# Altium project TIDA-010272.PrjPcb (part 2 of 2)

## Sheet Power.SchDoc
size 431 x 279 mm; Date: Not shown in title block; ApprovedBy: Not shown in title block; CheckedBy: Not shown in title block; Author: Not shown in title block; CompanyName: Not shown in title block; Engineer: Not shown in title block; Organization: Not shown in title block; Address1: Not shown in title block; Address2: Not shown in title block; Address3: Not shown in title block; Address4: Not shown in title block; DocumentNumber: 2; Revision: Use project parameter SCH_Rev; SheetNumber: 9; SheetTotal: 10; PageSetup: Record=PageOptions¦CenterHorizontal=True¦CenterVertical=True¦PrintScale=1.00¦XCorrection=1.00¦YCorrection=1.00¦PrintKind=0¦BorderSize=5000000¦LeftOffset=0¦BottomOffset=0¦Orientation=2¦PaperLength=1000¦PaperWidth=1000¦Scale=100¦PaperSource=15¦PrintQuality=600¦MediaType=1¦DitherType=10¦PaperKind=Letter¦PrintScaleMode=1; EVM_orderable: N/A
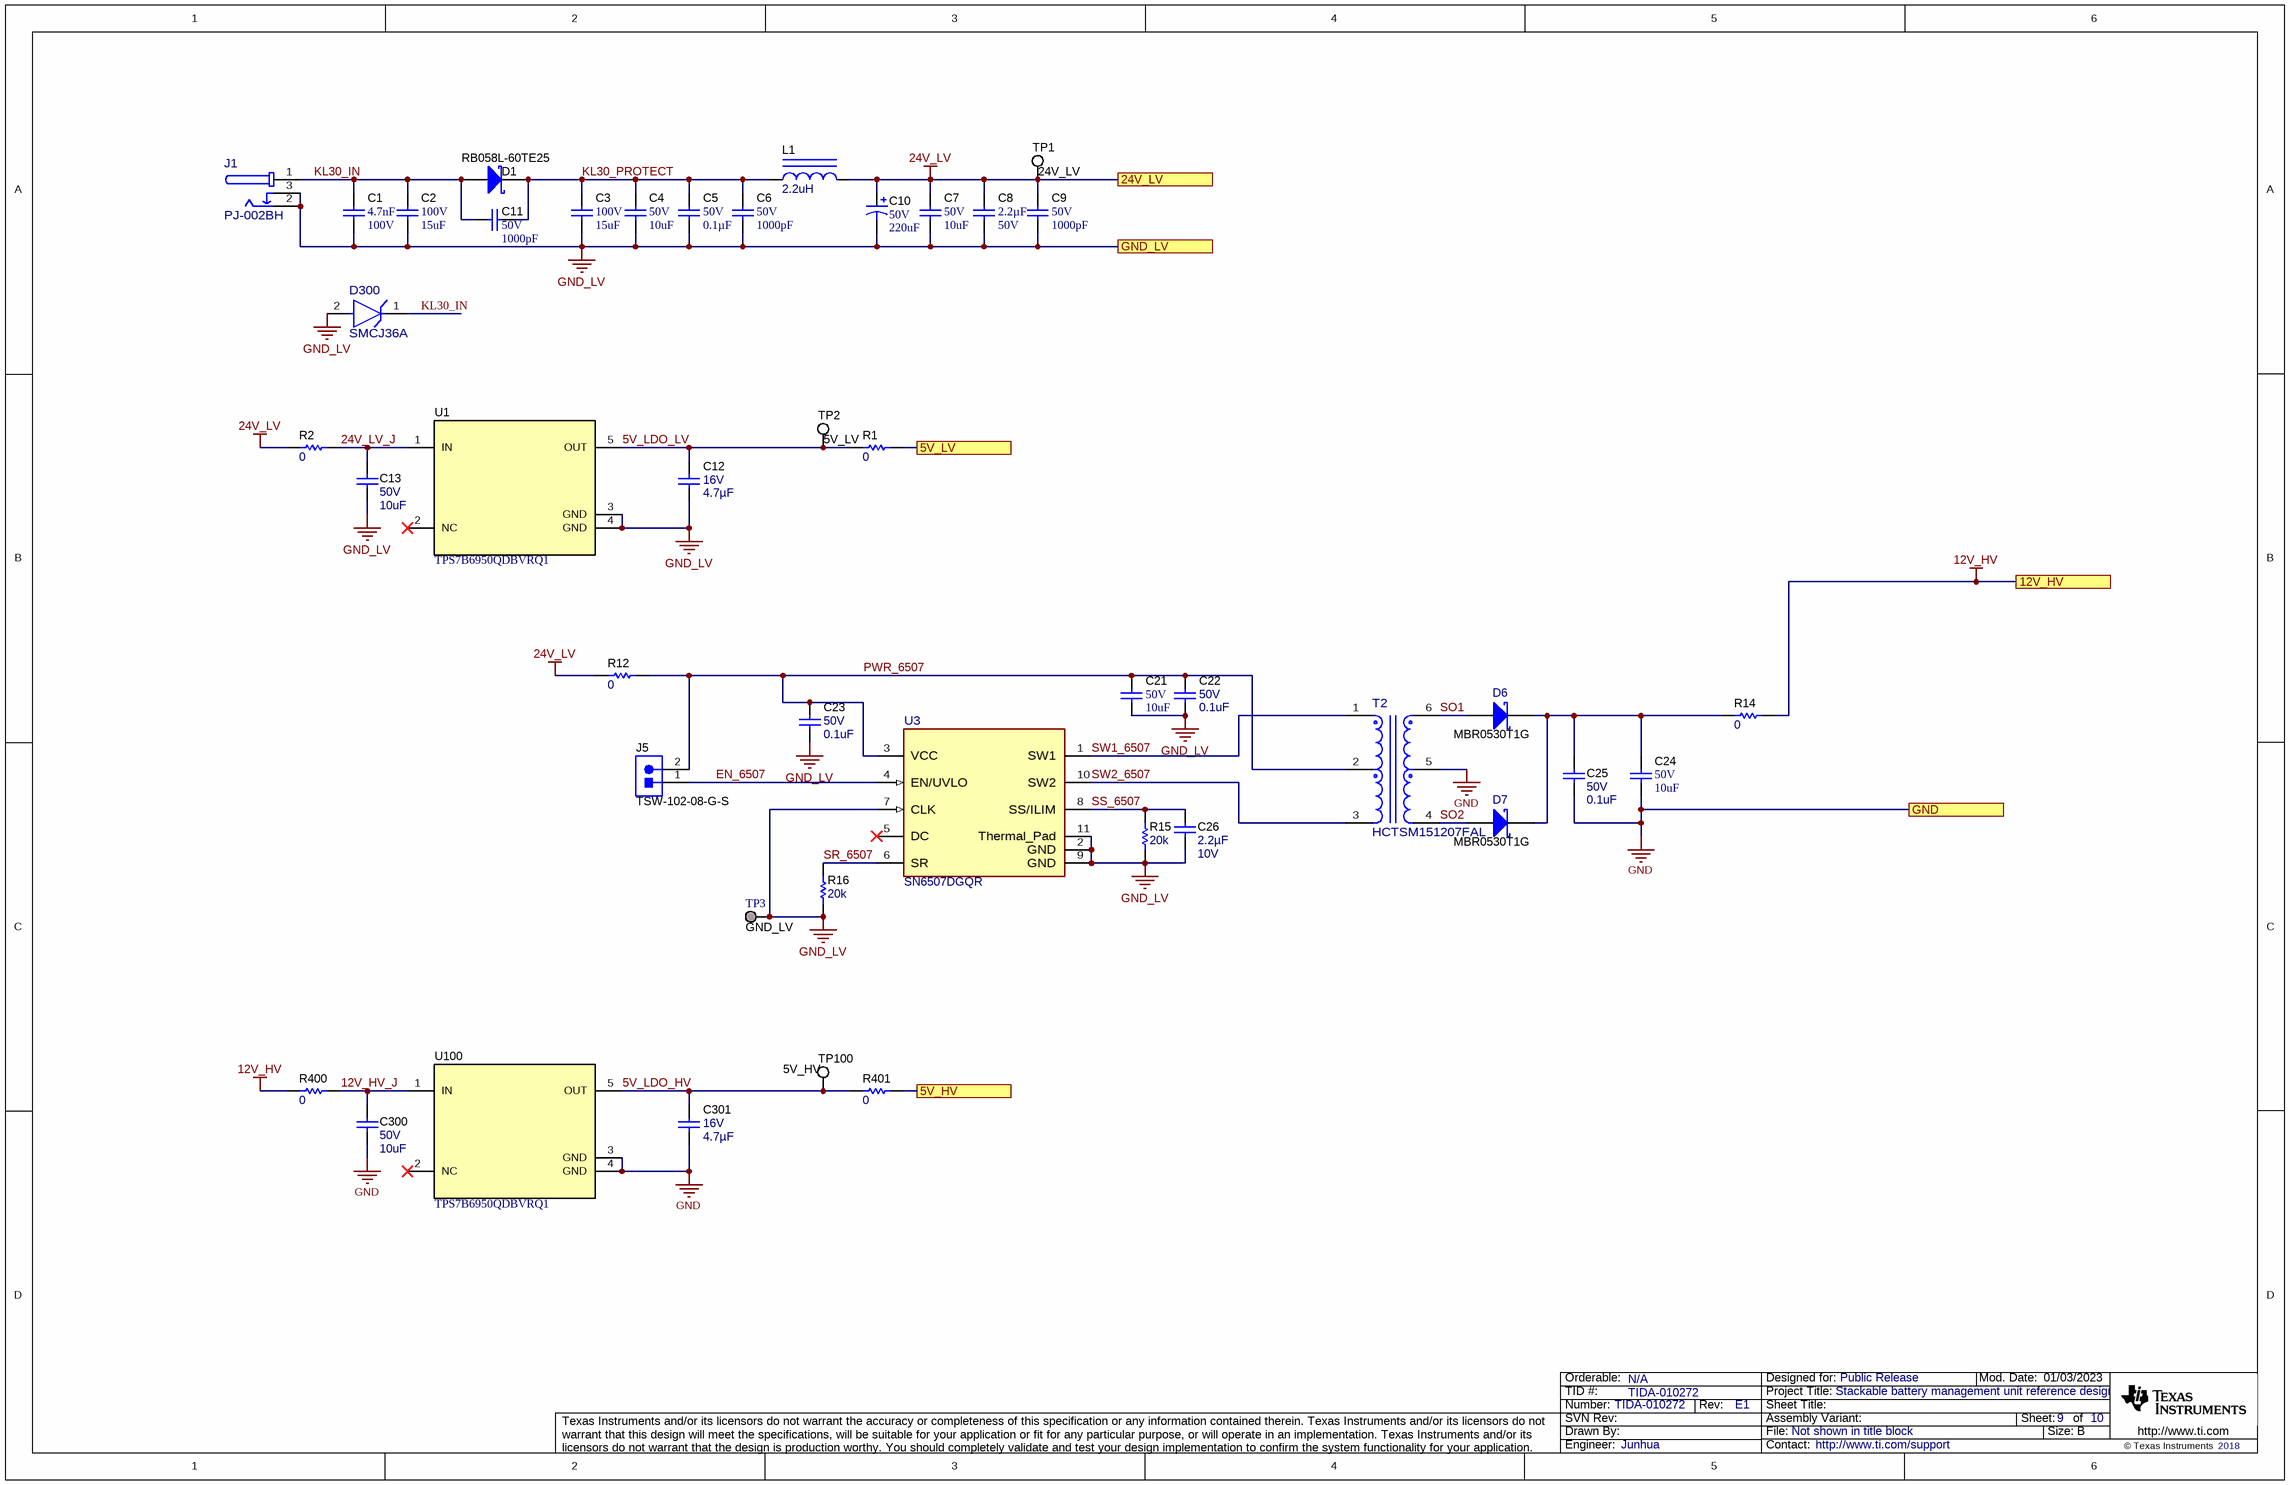
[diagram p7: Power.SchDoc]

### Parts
C1  Cap_F: 4.7nF  VDC_V: 100V  [0603]  (hidden comment: CGA3E2X7R2A472K080AA)
C2  VDC_V: 100V  ValueDisplayed: 15uF  [2220_280]  (hidden comment: CGA9P3X7S2A156M250KB)
C3  VDC_V: 100V  ValueDisplayed: 15uF  [2220_280]  (hidden comment: CGA9P3X7S2A156M250KB)
C4  VDC_V: 50V  ValueDisplayed: 10uF  [1210_280]  (hidden comment: CGA6P3X7S1H106K250AB)
C5  VDC_V: 50V  ValueDisplayed: 0.1µF  [0603]  (hidden comment: CGA3E3X8R1H104M080AB)
C6  VDC_V: 50V  ValueDisplayed: 1000pF  [0402]  (hidden comment: CGA2B2C0G1H102J050BA)
C7  VDC_V: 50V  ValueDisplayed: 10uF  [1210_280]  (hidden comment: CGA6P3X7S1H106K250AB)
C8  Cap_F: 2.2µF  VDC_V: 50V  [0805_HV]  (hidden comment: CGA4J3X7R1H225K125AB)
C9  VDC_V: 50V  ValueDisplayed: 1000pF  [0402]  (hidden comment: CGA2B2C0G1H102J050BA)
C10  VDC_V: 50V  ValueDisplayed: 220uF  [SM_RADIAL_G]  (hidden comment: EEE-FK1H221GP)
C11  VDC_V: 50V  ValueDisplayed: 1000pF  [0402]  (hidden comment: GRM1555C1H102JA01D)
C12  VDC_V: 16V  ValueDisplayed: 4.7µF  [0603]  (hidden comment: GRT188R61C475KE13D)
C13  VDC_V: 50V  ValueDisplayed: 10uF  [1206_180]  (hidden comment: GRT31CR61H106KE01L)
C21  VDC_V: 50V  ValueDisplayed: 10uF  [1210_280]  (hidden comment: CGA6P3X7S1H106K250AB)
C22  VDC_V: 50V  ValueDisplayed: 0.1uF  [0402]  (hidden comment: GCM155R71H104KE02D)
C23  VDC_V: 50V  ValueDisplayed: 0.1uF  [0402]  (hidden comment: GCM155R71H104KE02D)
C24  VDC_V: 50V  ValueDisplayed: 10uF  [1210_280]  (hidden comment: CGA6P3X7S1H106K250AB)
C25  VDC_V: 50V  ValueDisplayed: 0.1uF  [0402]  (hidden comment: GCM155R71H104KE02D)
C26  Cap_F: 2.2µF  VDC_V: 10V  [0603]  (hidden comment: GRM188R71A225KE15J)
C300  VDC_V: 50V  ValueDisplayed: 10uF  [1206_180]  (hidden comment: GRT31CR61H106KE01L)
C301  VDC_V: 16V  ValueDisplayed: 4.7µF  [0603]  (hidden comment: GRT188R61C475KE13D)
D1  RB058L-60TE25  [SMA]
D6  MBR0530T1G  [SOD-123]
D7  MBR0530T1G  [SOD-123]
D300  SMCJ36A  [FP-SMCJ36A_DO-214AB-MFG]
J1  PJ-002BH  [FP-PJ-002BH_PTH_POWER_CONN_14MM4_9MM0-MFG]
J5  TSW-102-08-G-S  [Samtec_TSW-102-08-x-S]
L1  ValueDisplayed: 2.2uH  [IHLP-1616BZ]  (hidden comment: IHLP1616BZER2R2M01)
R1  ValueDisplayed: 0  [0603]  (hidden comment: CRCW06030000Z0EA)
R2  ValueDisplayed: 0  [0603]  (hidden comment: CRCW06030000Z0EA)
R12  ValueDisplayed: 0  [0603]  (hidden comment: CRCW06030000Z0EA)
R14  ValueDisplayed: 0  [0603]  (hidden comment: CRCW06030000Z0EA)
R15  ValueDisplayed: 20k  [0402]  (hidden comment: CRCW040220K0JNED)
R16  ValueDisplayed: 20k  [0402]  (hidden comment: CRCW040220K0JNED)
R400  ValueDisplayed: 0  [0603]  (hidden comment: CRCW06030000Z0EA)
R401  ValueDisplayed: 0  [0603]  (hidden comment: CRCW06030000Z0EA)
T2  HCTSM151207FAL  [FP-HCTSM151207FAL_SMT_XFRMR_21MM3_15MM0-MFG]
TP1  24V_LV  [Keystone5012]
TP2  5V_LV  [Keystone5012]
TP3  GND_LV  [Keystone1598-2]
TP100  5V_HV  [Keystone5012]
U1  TPS7B6950QDBVRQ1  [DBV0005A_N]
U3  SN6507DGQR  [DGQ0010D-C01-MFG]
U100  TPS7B6950QDBVRQ1  [DBV0005A_N]

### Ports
5V_HV, 5V_LV, 12V_HV, 24V_LV, GND, GND_LV

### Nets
12V_HV: R14.2 R400.1 ; port 12V_HV  [project net HV12]
24V_LV: C7.1 C8.1 C9.1 C10.1(+) L1.2 R2.1 R12.1 TP1.1 ; port 24V_LV
GND: C24.2 C25.2 C300.2 C301.2 T2.5 U100.3(GND) U100.4(GND) ; port GND
GND_LV: C1.2 C2.2 C3.2 C4.2 C5.2 C6.2 C7.2 C8.2 C9.2 C10.2(-) C12.2 C13.2 C21.2 C22.2 C23.2 C26.2 D300.2(ANODE) J1.2 J1.3 R15.1 R16.1 TP3.1 U1.3(GND) U1.4(GND) U3.2(GND) U3.7(CLK) U3.9(GND) U3.11(Thermal_Pad) ; port GND_LV
5V_HV: R401.2 ; port 5V_HV
5V_LDO_HV: C301.1 R401.1 TP100.1 U100.5(OUT)
5V_LDO_LV: C12.1 R1.1 TP2.1 U1.5(OUT)
5V_LV: R1.2 ; port 5V_LV
12V_HV_J: C300.1 R400.2 U100.1(IN)
24V_LV_J: C13.1 R2.2 U1.1(IN)
EN_6507: J5.1 U3.4(EN/UVLO)
KL30_IN: C1.1 C2.1 C11.2 D1.2(A) D300.1(CATHODE) J1.1
KL30_PROTECT: C3.1 C4.1 C5.1 C6.1 C11.1 D1.1(K) L1.1
PWR_6507: C21.1 C22.1 C23.1 J5.2 R12.2 T2.2 U3.3(VCC)
SO1: D6.2(A) T2.6
SO2: D7.2(A) T2.4
SR_6507: R16.2 U3.6(SR)
SS_6507: C26.1 R15.2 U3.8(SS/ILIM)
SW1_6507: T2.1 U3.1(SW1)
SW2_6507: T2.3 U3.10(SW2)
NetC24_1: C24.1 C25.1 D6.1(K) D7.1(K) R14.1

Not connected (* = marked no-connect by the designer): U1 2(NC)*; U3 5(DC)*; U100 2(NC)*

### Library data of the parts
C1 = CMP-0007088-4: CAP, CERM, 4700 pF, 100 V, +/- 10%, X7R, AEC-Q200 Grade 1, 0603; Manufacturer: TDK; TaMin_C: -55°C; ESR_ohm: 0.469862; Polarized: N; SizeAreaWB_mm2: 4.68; Value1: 0.469862 ohm; U/M: EA; Value: 4700pF; TaMax_C: 125°C; SizeZ_mm: 1; SizeX_mm: 1.6; SizeY_mm: 0.8; SizeArea_mm2: 1.28; AEC Qualified: Y; IRMS_A: 323.35mA; AEC Category: Q200
C2 C3 = CMP-0009420-2: CAP, CERM, 15 uF, 100 V, +/- 20%, X7S, AEC-Q200 Grade 1, 2220; Manufacturer: TDK; TaMin_C: -55°C; ESR_ohm: 2.642m; Polarized: N; SizeAreaWB_mm2: 53.9; Value1: 0.002642 ohm; U/M: EA; Value: 15uF; TaMax_C: 125°C; SizeZ_mm: 2.8; SizeX_mm: 5.7; SizeY_mm: 5; SizeArea_mm2: 28.5; AEC Qualified: Y; Cap_F: 15µF; IRMS_A: 5.61617A; AEC Grade: 1; AEC Category: Q200
C4 C7 C21 C24 = CMP-0009164-2: CAP, CERM, 10 uF, 50 V, +/- 10%, X7S, AEC-Q200 Grade 1, 1210; Manufacturer: TDK; TaMin_C: -55°C; ESR_ohm: 2.827m; Polarized: N; SizeAreaWB_mm2: 14.7; Value1: 0.002827 ohm; U/M: EA; Value: 10uF; TaMax_C: 125°C; SizeZ_mm: 2.8; SizeX_mm: 3.2; SizeY_mm: 2.5; SizeArea_mm2: 8; AEC Qualified: Y; Cap_F: 10µF; IRMS_A: 4.37286A; AEC Grade: 1; AEC Category: Q200
C5 = CMP-0084240-1: CAP, CERM, 0.1 µF, 50 V,+/- 20%, X8R, AEC-Q200 Grade 0, 0603; Manufacturer: TDK; TaMin_C: -55°C; Polarized: N; SizeAreaWB_mm2: 4.68; U/M: EA; Value: 0.1uF; TaMax_C: 150°C; SizeZ_mm: 1; SizeX_mm: 1.6; SizeY_mm: 0.8; SizeArea_mm2: 1.28; AEC Qualified: Y; Cap_F: 100nF; AEC Grade: 0; AEC Category: Q200
C6 C9 = CMP-0006309-2: CAP, CERM, 1000 pF, 50 V, +/- 5%, C0G/NP0, AEC-Q200 Grade 1, 0402; Manufacturer: TDK; TaMin_C: -55°C; Polarized: N; SizeAreaWB_mm2: 3; Value1: Unknown; U/M: EA; Value: 1000pF; TaMax_C: 125°C; SizeZ_mm: 0.6; SizeX_mm: 1; SizeY_mm: 0.5; AEC Qualified: Y; Cap_F: 1nF; AEC Category: Q200
C8 = CMP-0007977-2: CAP, CERM, 2.2 uF, 50 V, +/- 10%, X7R, AEC-Q200 Grade 1, 0805; Manufacturer: TDK; TaMin_C: -55°C; ESR_ohm: 3.288m; Polarized: N; SizeAreaWB_mm2: 6.75; Value1: 0.003288 ohm; U/M: EA; Value: 2.2uF; TaMax_C: 125°C; SizeZ_mm: 1.45; SizeX_mm: 2; SizeY_mm: 1.25; Cap_Case: 0805; SizeArea_mm2: 2.5; AEC Qualified: Y; IRMS_A: 3.60029A; AEC Grade: 1; AEC Category: Q200
C10 = CMP-0011180-2: CAP, AL, 220 uF, 50 V, +/- 20%, 0.18 ohm, AEC-Q200 Grade 2, SMD; Manufacturer: Panasonic; TaMin_C: -55°C; ESR_ohm: 1.8d; Polarized: Y; SizeAreaWB_mm2: 172.2; U/M: EA; Value: 220uF; TaMax_C: 105°C; SizeZ_mm: 10.2; SizeX_mm: 12; SizeY_mm: 10.3; Cap_Case: G; SizeArea_mm2: 123.6; CompType: Capacitor; Cap_F: 220µF; IRMS_A: 6.7dA; AEC Grade: 2; AEC Category: Q200
C11 = CMP-0006412-2: CAP, CERM, 1000 pF, 50 V, +/- 5%, C0G/NP0, 0402; Manufacturer: MuRata; TaMin_C: -55°C; Polarized: N; SizeAreaWB_mm2: 3; Value1: Unknown; U/M: EA; Value: 1000pF; TaMax_C: 125°C; SizeZ_mm: 0.6; SizeX_mm: 1; SizeY_mm: 0.5; Cap_F: 1nF; AEC Category: Q200
C12 C301 = CMP-0081052-1: CAP, CERM, 4.7 µF, 16 V,+/- 10%, X5R, AEC-Q200 Grade 3, 0603; Manufacturer: MuRata; SizeAreaWB_mm2: 4.68; SizeArea_mm2: 1.28; AEC Qualified: Y; AEC Category: Q200; Value: 4.7uF; TaMax_C: 85°C; SizeZ_mm: 1; AEC Grade: 3; Polarized: N; TaMin_C: -55°C; SizeY_mm: 0.8; U/M: EA; SizeX_mm: 1.6
C13 C300 = CMP-0009015-2: CAP, CERM, 10 uF, 50 V, +/- 10%, X5R, AEC-Q200 Grade 1, 1206; Manufacturer: MuRata; TaMin_C: -55°C; Polarized: N; SizeAreaWB_mm2: 10.92; Value1: Unknown; U/M: EA; Value: 10uF; TaMax_C: 85°C; SizeZ_mm: 1.8; SizeX_mm: 3.2; SizeY_mm: 1.6; Cap_Case: 1206; SizeArea_mm2: 5.12; AEC Qualified: Y; Cap_F: 10µF; AEC Grade: 1; AEC Category: Q200
C22 C23 C25 = CMP-0006356-2: CAP, CERM, 0.1 uF, 50 V, +/- 10%, X7R, AEC-Q200 Grade 1, 0402; Manufacturer: MuRata; TaMin_C: -55°C; Polarized: N; SizeAreaWB_mm2: 3; Value1: Unknown; U/M: EA; Value: 0.1uF; TaMax_C: 125°C; SizeZ_mm: 0.6; SizeX_mm: 1; SizeY_mm: 0.5; AEC Qualified: Y; Cap_F: 100nF; AEC Category: Q200
C26 = CMP-0084284-1: CAP, CERM, 2.2 µF, 10 V,+/- 10%, X7R, AEC-Q200 Grade 1, 0603; Manufacturer: MuRata; SizeAreaWB_mm2: 4.68; Polarized: N; AEC Qualified: Y; SizeX_mm: 1.6; SizeZ_mm: 1; SizeY_mm: 0.8; U/M: EA; TaMin_C: -55°C; Value: 2.2uF; AEC Category: Q200; TaMax_C: 125°C; SizeArea_mm2: 1.28
D1 = CMP-0028854-2: Diode, Schottky, 60 V, 3 A, AEC-Q101, SMA; Manufacturer: Rohm; Value1: 3A; AEC Category: Q101; Green_REACh: Incomplete; TJmax_C: 150°C; SizeArea_mm2: 16.3228; Vf_V: 640mV; SizeZ_mm: 2.87; Value2: 0.64V; Value: 60V; SizeX_mm: 5.59; AEC Qualified: Y; Green_Lifecycle: Not Set; SizeAreaWB_mm2: 37.3428; SizeY_mm: 2.92
D6 D7 = CMP-0028525-2: Diode, Schottky, 30 V, 0.5 A, SOD-123; Manufacturer: ON Semiconductor; Value: 30V; SizeZ_mm: 1.35; SizeAreaWB_mm2: 13.095; Value2: 0.43V; Green_REACh: Passed; Io_A: 500mA; SizeArea_mm2: 6.545; TJmax_C: 125°C; Green_Lifecycle: Active; RJC_CperW: 150; SizeX_mm: 3.85; AEC Category: Q101; SizeY_mm: 1.7; Vf_V: 430mV; Value1: 0.5A
D300 = CMP-0089183-1: TVS DIODE 36VWM 58.1VC SMC; Manufacturer: Littelfuse; Breakdown Voltage: 40V; TJmax_C: +150°C; SizeZ_mm: 2.62mm; Direction: Unidirectional; Ppk: 1.5kW; Number Of Channels: 1; AEC Qualified: No; Clamping Voltage: 58.1V; VRWM: 36V; Ipp: 25.9A
J1 = CMP-0091947-1: Manufacturer: CUI Devices; AEC Qualified: No; SizeZ_mm: 11.2mm; Conn Orientation: Right Angle; ContactFinish: Nickel; Voltage_V: 24V; Conn Gender: Male; Current_A: 5A
J5 = CMP-0077643-1: Header, 2.54mm, 2x1, Gold, TH; Manufacturer: Samtec; Pitch_mm: 2.54; Gender: Male; Cert_CSA: Y; Current_A: 5.7A; Voltage_V: 550V; Row_Count: 1
L1 = CMP-0063278-1: Inductor, Shielded Drum Core, Powdered Iron, 2.2 uH, 2.85 A, 0.08 ohm, SMD; Manufacturer: Vishay-Dale; Isat: 6A @ 20% inductance drop; Irms: 2.85A @ 40C rise; Green_Lifecycle: Active; SizeAreaWB_mm2: 27.577; DCR_ohm: 0.08; Green_REACh: Passed; Value: 2.2uH; Imax_A: 2.85A; SizeZ_mm: 2; SizeX_mm: 4.45; SizeY_mm: 4.06; SizeArea_mm2: 18.067; Ind_H: 2.2µH; AEC Category: Q200
R1 R2 R12 R14 R400 R401 = CMP-0025697-4: RES, 0, 5%, 0.1 W, AEC-Q200 Grade 0, 0603; Manufacturer: Vishay-Dale; Power_W: 100mW; TempCo: 200 ppm/C; Value_Code: 0000; Value: 0; EIA_Code: E24; SizeX_mm: 1.6; SizeY_mm: 0.8; SizeZ_mm: 1; Value2: 0.1W; SizeArea_mm2: 1.28; AEC Qualified: Y; VDC_V: 75V; AEC Category: Q200
R15 R16 = CMP-0026875-3: RES, 20 k, 5%, 0.063 W, AEC-Q200 Grade 0, 0402; Manufacturer: Vishay-Dale; Power_W: 63mW; TempCo: 200 ppm/C; Value_Code: 20k0; Value: 20k; EIA_Code: E24; SizeX_mm: 1; SizeY_mm: 0.5; SizeZ_mm: 0.6; Value2: 0.063W; AEC Qualified: Y; VDC_V: 50V; AEC Category: Q200; AEC Grade: 0
T2 = CMP-0120536-1: High Clearance and Creepage Transformer; Manufacturer: Bourns; DCR_ohm: 1.5; Ind_H: 400µH; Ns1toNp: 0.583; Rsec1_ohm: 1; SizeZ_mm: 10.1mm; AEC Qualified: Yes; AEC Grade: Grade 0; Frequency_Fixed: 100-2000kHz; Voltage_Isolation_Vrms: 7.64kVDC
TP1 TP2 TP100 = CMP-0055149-1: Test Point, Multipurpose, White, TH; PartNumber: 5012; Manufacturer: Keystone; ContactFinish: Silver; CNHeader: FALSE; Green_Lifecycle: Active; Green_REACh: Passed; CT: TRUE
TP3 = CMP-0055121-1: Terminal, Turret, TH, Triple; Manufacturer: Keystone; PartNumber: 1598-2; CT: FALSE; Green_REACh: Passed; CompType: Turret Terminal; Green_Lifecycle: Active
U1 U100 = CMP-0077329-2: Automotive High-Voltage Ultra-Low IQ Low-Dropout Regulator/Fixed 5-V Output Voltage, DBV0005A (SOT-23-5); Manufacturer: Texas Instruments; SizeArea_mm2: 8.12; CompType: IC; SizeAreaWB_mm2: 14.82; SizeY_mm: 2.9; SizeZ_mm: 1.45; SizeX_mm: 2.8; AEC Category: Q200; AEC Qualified: Y
U3 = CMP-0095407-1: Low-Emission 36V Push-Pull Transformer Driver with Duty Cycle Control for Isolated Power Supplies; Manufacturer: Texas Instruments; AEC Qualified: No; TJmax_C: +150°C; TaMin_C: -55°C; TaMax_C: +125°C; Standoff Height: 0.05mm; SizeZ_mm: 1.1mm

## Sheet UIR_Board_Hardware.SchDoc
size 431 x 279 mm; Date: Not shown in title block; ApprovedBy: Not shown in title block; CheckedBy: Not shown in title block; Author: Not shown in title block; CompanyName: Not shown in title block; Engineer: Not shown in title block; Organization: Not shown in title block; Address1: Not shown in title block; Address2: Not shown in title block; Address3: Not shown in title block; Address4: Not shown in title block; DocumentNumber: 3; Revision: Use project parameter SCH_Rev; SheetNumber: 10; SheetTotal: 10; PageSetup: Record=PageOptions¦CenterHorizontal=True¦CenterVertical=True¦PrintScale=1.00¦XCorrection=1.00¦YCorrection=1.00¦PrintKind=0¦BorderSize=5000000¦LeftOffset=0¦BottomOffset=0¦Orientation=2¦PaperLength=1000¦PaperWidth=1000¦Scale=100¦PaperSource=15¦PrintQuality=600¦MediaType=1¦DitherType=10¦PaperKind=Letter¦PrintScaleMode=1
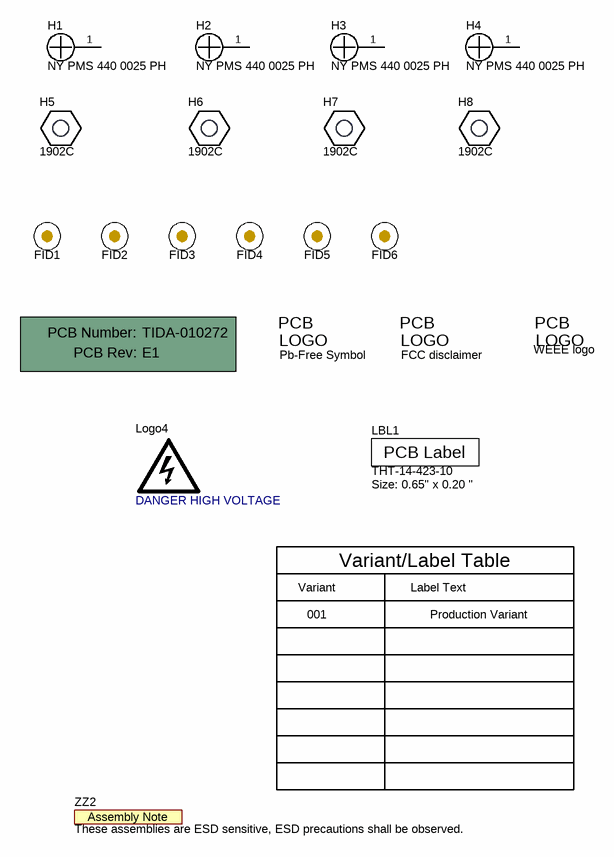
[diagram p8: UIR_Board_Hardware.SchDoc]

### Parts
!PCB1  Printed Circuit Board  (value not drawn)  (mechanical)
FID1  Fiducial  [Fiducial10-20]  (value not drawn)
FID2  Fiducial  [Fiducial10-20]  (value not drawn)
FID3  Fiducial  [Fiducial10-20]  (value not drawn)
FID4  Fiducial  [Fiducial10-20]  (value not drawn)
FID5  Fiducial  [Fiducial10-20]  (value not drawn)
FID6  Fiducial  [Fiducial10-20]  (value not drawn)
H1  NY PMS 440 0025 PH  [NY PMS 440 0025 PH]
H2  NY PMS 440 0025 PH  [NY PMS 440 0025 PH]
H3  NY PMS 440 0025 PH  [NY PMS 440 0025 PH]
H4  NY PMS 440 0025 PH  [NY PMS 440 0025 PH]
H5  1902C  [Keystone_1902C]
H6  1902C  [Keystone_1902C]
H7  1902C  [Keystone_1902C]
H8  1902C  [Keystone_1902C]
LBL1  THT-14-423-10  Note: Size: 0.65" x 0.20 "  [Label_650x200]
Logo2  Pb-Free Symbol  [Pb-Free_Overlay_Small]  (no BOM)
Logo3  FCC disclaimer  [FCC_disclaimer]  (no BOM)
Logo4  DANGER HIGH VOLTAGE  [IEC_HighVoltage_Small]  (no BOM)
Logo5  WEEE logo  [WEEE_Minimum]  (no BOM)
ZZ2  These assemblies are ESD sensitive, ESD precautions shall be observed.  [AssemblyNote]  (no BOM)

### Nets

Not connected (* = marked no-connect by the designer): H1 1; H2 1; H3 1; H4 1

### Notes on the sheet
- Variant
- Variant/Label Table
- Label Text
- 001
- Production Variant

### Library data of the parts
!PCB1 = CMP-0003618-2: Manufacturer: Any; PartNumber: TIDA-010272
FID1-FID6 = CMP-0077181-1: Fiducial mark.  There is nothing to buy or mount.
H1-H4 = CMP-0003617-1: Machine Screw, Round, #4-40 x 1/4, Nylon, Philips panhead; Manufacturer: B&F Fastener Supply; CompType: Hardware
H5-H8 = CMP-0003610-1: Standoff, Hex, 0.5"L #4-40 Nylon; Manufacturer: Keystone; CompType: Hardware
LBL1 = CMP-0003625-1: Thermal Transfer Printable Labels, 0.650" W x 0.200" H - 10,000 per roll; Manufacturer: Brady; CompType: Label
Logo2 = CMP-0074839-1: SymbolCreator: a0412235; Library Reference: Logo
Logo3 = CMP-0074847-1: FCC_disclaimer; Library Reference: Logo
Logo4 = CMP-0074835-1: IEC 61010-1 High Voltage Warning; SymbolCreator: a0412235
Logo5 = CMP-0074769-1
ZZ2 = CMP-0077236-1

## Sheet ISOMonitor.SchDoc
size 558 x 431 mm; SheetNumber: 6; SheetTotal: 10
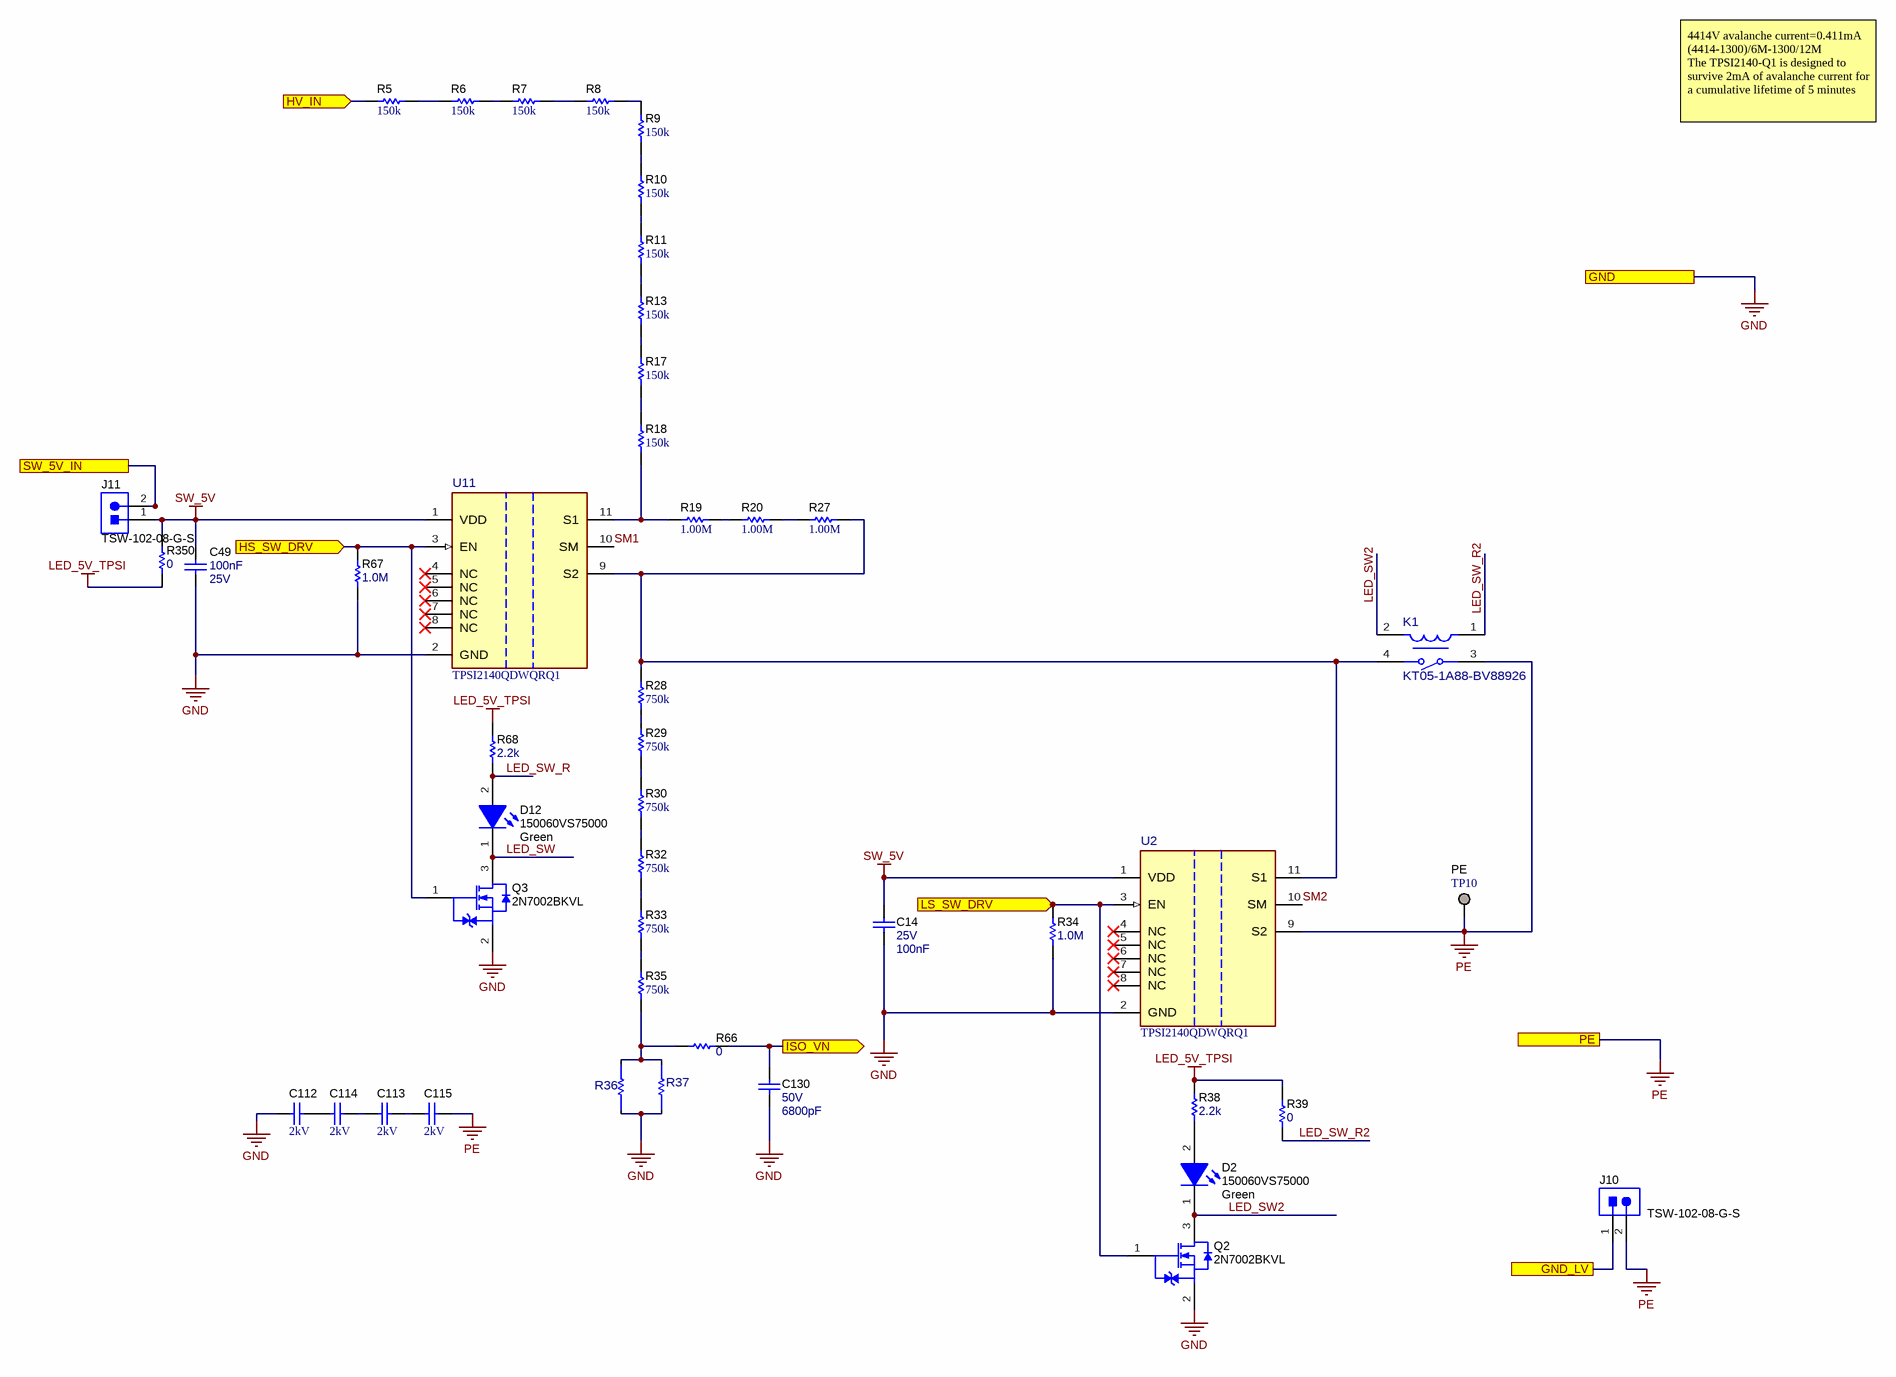
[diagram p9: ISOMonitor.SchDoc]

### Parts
C14  VDC_V: 25V  Cap_F: 100nF  [0603]  (hidden comment: GCM188R71E104KA57D)
C49  VDC_V: 25V  Cap_F: 100nF  [0603]  (hidden comment: GCM188R71E104KA57D)
C112  VDC_V: 2kV  [1206_180]  (hidden comment: 1206J2K00220KCT)
C113  VDC_V: 2kV  [1206_180]  (hidden comment: 1206J2K00220KCT)
C114  VDC_V: 2kV  [1206_180]  (hidden comment: 1206J2K00220KCT)
C115  VDC_V: 2kV  [1206_180]  (hidden comment: 1206J2K00220KCT)
C130  VDC_V: 50V  ValueDisplayed: 6800pF  [0603]  (hidden comment: GRM1885C1H682JA01D)
D2  150060VS75000  value Green  [WL-SMCW_GREEN]
D12  150060VS75000  value Green  [WL-SMCW_GREEN]
J10  TSW-102-08-G-S  [Samtec_TSW-102-08-x-S]
J11  TSW-102-08-G-S  [Samtec_TSW-102-08-x-S]
K1  KT05-1A88-BV88926  [FP-KT05-1A88-BV88926_SMT_RELAY_10MM2_30MM2-MFG]
Q2  2N7002BKVL  [SOT-23L]
Q3  2N7002BKVL  [SOT-23L]
R5  ValueDisplayed: 150k  [1206]  (hidden comment: CRCW1206150KJNEA)
R6  ValueDisplayed: 150k  [1206]  (hidden comment: CRCW1206150KJNEA)
R7  ValueDisplayed: 150k  [1206]  (hidden comment: CRCW1206150KJNEA)
R8  ValueDisplayed: 150k  [1206]  (hidden comment: CRCW1206150KJNEA)
R9  ValueDisplayed: 150k  [1206]  (hidden comment: CRCW1206150KJNEA)
R10  ValueDisplayed: 150k  [1206]  (hidden comment: CRCW1206150KJNEA)
R11  ValueDisplayed: 150k  [1206]  (hidden comment: CRCW1206150KJNEA)
R13  ValueDisplayed: 150k  [1206]  (hidden comment: CRCW1206150KJNEA)
R17  ValueDisplayed: 150k  [1206]  (hidden comment: CRCW1206150KJNEA)
R18  ValueDisplayed: 150k  [1206]  (hidden comment: CRCW1206150KJNEA)
R19  ValueDisplayed: 1.00M  [1206]  (hidden comment: ERJ-8ENF1004V)
R20  ValueDisplayed: 1.00M  [1206]  (hidden comment: ERJ-8ENF1004V)
R27  ValueDisplayed: 1.00M  [1206]  (hidden comment: ERJ-8ENF1004V)
R28  ValueDisplayed: 750k  [TNPV1206]  (hidden comment: TNPV1206750KBEEN)
R29  ValueDisplayed: 750k  [TNPV1206]  (hidden comment: TNPV1206750KBEEN)
R30  ValueDisplayed: 750k  [TNPV1206]  (hidden comment: TNPV1206750KBEEN)
R32  ValueDisplayed: 750k  [TNPV1206]  (hidden comment: TNPV1206750KBEEN)
R33  ValueDisplayed: 750k  [TNPV1206]  (hidden comment: TNPV1206750KBEEN)
R34  ValueDisplayed: 1.0M  [0603]  (hidden comment: CRCW06031M00JNEA)
R35  ValueDisplayed: 750k  [TNPV1206]  (hidden comment: TNPV1206750KBEEN)
R36  PTFR0603B24K9NT  [FP-PTFR0603B24K9NT_0603-MFG]  (value not drawn)
R37  PTFR0603B24K9NT  [FP-PTFR0603B24K9NT_0603-MFG]  (value not drawn)
R38  ValueDisplayed: 2.2k  [0603]  (hidden comment: CRCW06032K20JNEA)
R39  ValueDisplayed: 0  [0603]  (hidden comment: CRCW06030000Z0EA)
R66  ValueDisplayed: 0  [0603]  (hidden comment: CRCW06030000Z0EA)
R67  ValueDisplayed: 1.0M  [0603]  (hidden comment: CRCW06031M00JNEA)
R68  ValueDisplayed: 2.2k  [0603]  (hidden comment: CRCW06032K20JNEA)
R350  ValueDisplayed: 0  [0603]  (hidden comment: CRCW06030000Z0EA)
TP10  PE  [Keystone1598-2]
U2  TPSI2140QDWQRQ1  [DWQ0011A-MFG]
U11  TPSI2140QDWQRQ1  [DWQ0011A-MFG]

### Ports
GND, GND_LV, HS_SW_DRV (in), HV_IN (in), ISO_VN (out), LS_SW_DRV (in), PE, SW_5V_IN

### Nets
AVDD: J11.2 ; port SW_5V_IN
GND: C14.2 C49.2 C112.2 C130.2 Q2.2(S) Q3.2(S) R34.1 R36.1 R37.1 R67.1 U2.2(GND) U11.2(GND) ; port GND
GND_LV: J10.1 ; port GND_LV
LED_5V_TPSI: R38.2 R39.1 R68.2 R350.2
PE: C115.1 J10.2 K1.3 TP10.1 U2.9(S2) ; port PE
SW_5V: C14.1 C49.1 J11.1 R350.1 U2.1(VDD) U11.1(VDD)
BATP_L: R5.2 ; port HV_IN
HS_SW_DRV: Q3.1(G) R67.2 U11.3(EN) ; port HS_SW_DRV
ISO_VN: C130.1 R66.1 ; port ISO_VN
LED_SW: D12.1(K) Q3.3(D)
LED_SW2: D2.1(K) K1.2 Q2.3(D)
LED_SW_R: D12.2(A) R68.1
LED_SW_R2: K1.1 R39.2
LS_SW_DRV: Q2.1(G) R34.2 U2.3(EN) ; port LS_SW_DRV
SM1: U11.10(SM)
SM2: U2.10(SM)
NetC112_1: C112.1 C114.2
NetC113_1: C113.1 C115.2
NetC113_2: C113.2 C114.1
NetD2_2: D2.2(A) R38.1
NetK1_4: K1.4 R27.2 R28.2 U2.11(S1) U11.9(S2)
NetR5_1: R5.1 R6.2
NetR6_1: R6.1 R7.2
NetR7_1: R7.1 R8.2
NetR8_1: R8.1 R9.2
NetR9_1: R9.1 R10.2
NetR10_1: R10.1 R11.2
NetR11_1: R11.1 R13.2
NetR13_1: R13.1 R17.2
NetR17_1: R17.1 R18.2
NetR18_1: R18.1 R19.1 U11.11(S1)
NetR19_2: R19.2 R20.1
NetR20_2: R20.2 R27.1
NetR28_1: R28.1 R29.2
NetR29_1: R29.1 R30.2
NetR30_1: R30.1 R32.2
NetR32_1: R32.1 R33.2
NetR33_1: R33.1 R35.2
NetR35_1: R35.1 R36.2 R37.2 R66.2

Not connected (* = marked no-connect by the designer): U2 4(NC)* 5(NC)* 6(NC)* 7(NC)* 8(NC)*; U11 4(NC)* 5(NC)* 6(NC)* 7(NC)* 8(NC)*

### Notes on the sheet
- 4414V avalanche current=0.411mA	(4414-1300)/6M-1300/12M
  The TPSI2140-Q1 is designed to survive 2mA of avalanche current for a cumulative lifetime of 5 minutes

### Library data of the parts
C14 C49 = CMP-0084679-1: CAP, CERM, 0.1 µF, 25 V,+/- 10%, X7R, AEC-Q200 Grade 1, 0603; Manufacturer: MuRata; TaMin_C: -55°C; SizeY_mm: 0.8; Polarized: N; SizeArea_mm2: 1.28; SizeZ_mm: 1; SizeX_mm: 1.6; AEC Qualified: Y; AEC Category: Q200; Value: 0.1uF; ValueDisplayed: 0.1µF; TaMax_C: 125°C; U/M: EA; SizeAreaWB_mm2: 4.68
C112-C115 = CMP-0077201-1: CAP, CERM, 2200 pF, 2000 V,+/- 10%, X7R, AEC-Q200 Grade 1, 1206; Manufacturer: Knowles Capacitors; PartNumber: C1206C102KGRACAUTO; TaMin_C: -55°C; Polarized: N; SizeAreaWB_mm2: 10.92; U/M: EA; Value: 22pF; TaMax_C: 125°C; SizeZ_mm: 1.8; SizeX_mm: 3.2; SizeY_mm: 1.6; Cap_Case: 1206; Value2: 2000V; SizeArea_mm2: 5.12; AEC Qualified: Y; Cap_F: 2.2nF; AEC Grade: 1; AEC Category: Q200
C130 = CMP-0078296-1: CAP, CERM, 6800 pF, 50 V,+/- 5%, C0G/NP0, 0603; Manufacturer: MuRata; TaMin_C: -55°C; Polarized: N; SizeAreaWB_mm2: 4.68; U/M: EA; Value: 6800pF; TaMax_C: 125°C; SizeZ_mm: 1; SizeX_mm: 1.6; SizeY_mm: 0.8; SizeArea_mm2: 1.28; Cap_F: 6.8nF; AEC Category: Q200
D2 D12 = CMP-0002894-2: LED, Green, SMD; Manufacturer: Wurth Elektronik; Type: AlInGaP; Value2: 2V; Io_A: 20mA; Value1: W
J10 J11 = CMP-0077643-1: as J5 on sheet Power
K1 = CMP-0122333-1: Reed Relay 5VDC 80Ohm 1.5A SPST-NO(30.2x10.2x8.7)mm SMT; Manufacturer: Standex Electronics; Coil Power_W: 313mW; Coil Type: Non-Latching; Coil Voltage_VDC: 5V; Contact Rating_A: 3A; SizeZ_mm: 8.7mm; AEC Qualified: No; Coil Resistance: 80Ω; Standoff Height: 0.1mm
Q2 Q3 = CMP-0750155-1: MOSFET, N-CH, 60 V, 0.35 A, AEC-Q101, SOT-23; Manufacturer: Nexperia; Alternate Manufacturer: None; AEC Qualified: Y; SizeZ_mm: 1.1; Value2: 0.5 nC; SizeArea_mm2: 7.5; AEC Category: Q101; VdsMax_V: 60V; SizeX_mm: 2.5; Value: 60V; IdsMax_A: 350mA; ChMode: Enhancement; SizeAreaWB_mm2: 14; Vgs_V: 20V; QgTyp_nC: 0.5; Value1: ? ohm; ChType: N; SizeY_mm: 3
R5-R11 R13 R17 R18 = CMP-0018591-3: RES, 150 k, 5%, 0.25 W, AEC-Q200 Grade 0, 1206; Manufacturer: Vishay-Dale; Power_W: 250mW; TempCo: 200 ppm/C; Value: 150k; EIA_Code: E24; SizeX_mm: 3.2; SizeY_mm: 1.6; SizeZ_mm: 1.35; Value2: 0.25W; SizeArea_mm2: 5.12; AEC Qualified: Y; VDC_V: 200V; AEC Category: Q200; AEC Grade: 0
R19 R20 R27 = CMP-0017286-3: RES, 1.00 M, 1%, 0.25 W, AEC-Q200 Grade 0, 1206; Manufacturer: Panasonic; Power_W: 250mW; TempCo: 100 ppm/C; Value_Code: 1M00; Value: 1.00Meg; EIA_Code: E96; Res_ohm: 1M; SizeX_mm: 3.2; SizeY_mm: 1.6; SizeZ_mm: 1.35; Value2: 0.25W; SizeArea_mm2: 5.12; AEC Qualified: Y; VDC_V: 200V; AEC Category: Q200; AEC Grade: 0; SizeAreaWB_mm2: 10.92
R28-R30 R32 R33 R35 = CMP-0018817-2: RES, 750 k, 0.1%, 1 W, 1206; Manufacturer: Vishay Draloric; Power_W: 1W; TempCo: 25 ppm/C; U/M: EA; Value: 750k; EIA_Code: E192; SizeX_mm: 3.2; SizeY_mm: 1.6; SizeZ_mm: 0.65; SizeArea_mm2: 5.12; AEC Qualified: N; VDC_V: 700V; AEC Category: Q200
R34 R67 = CMP-0025736-4: RES, 1.0 M, 5%, 0.1 W, AEC-Q200 Grade 0, 0603; Manufacturer: Vishay-Dale; Power_W: 100mW; TempCo: 200 ppm/C; Value_Code: 1M00; Value: 1.0Meg; EIA_Code: E24; Res_ohm: 1M; SizeX_mm: 1.6; SizeY_mm: 0.8; SizeZ_mm: 1; Value2: 0.1W; SizeArea_mm2: 1.28; AEC Qualified: Y; VDC_V: 75V; AEC Category: Q200; AEC Grade: 0
R36 R37 = CMP-0122375-1: High-Stability Precision Thin Film Chip Resistor 24.9kOhm .1% 0603; Manufacturer: RESI; AEC Grade: Grade 0; AEC Qualified: Yes; Power_W: 170mW; Res_ohm: 24.9k; SizeZ_mm: 0.5mm; TempCo: 10ppm/°C; Tolerance_%: 0.1%; VDC_V: 100V; Value: 24.9k
R38 R68 = CMP-0025769-4: RES, 2.2 k, 5%, 0.1 W, AEC-Q200 Grade 0, 0603; Manufacturer: Vishay-Dale; Power_W: 100mW; TempCo: 200 ppm/C; Value_Code: 2k20; Value: 2.2k; EIA_Code: E24; SizeX_mm: 1.6; SizeY_mm: 0.8; SizeZ_mm: 1; Value2: 0.1W; SizeArea_mm2: 1.28; AEC Qualified: Y; VDC_V: 75V; AEC Category: Q200; AEC Grade: 0
R39 R66 R350 = CMP-0025697-4: as R1 on sheet Power
TP10 = CMP-0055121-1: as TP3 on sheet Power
U2 U11 = CMP-0090961-3: Isolated Solid State Relay; Manufacturer: Texas Instruments; CompType: IC; Output Voltage: 1400V; On State Resistance: 85Ω; Standoff Height: 0.1mm; TaMax_C: +125°C; Voltage_Isolation_Vrms: 1414VDC; AEC Grade: Grade 1; AEC Qualified: Yes; SizeZ_mm: 2.65mm; TJmax_C: +150°C; TaMin_C: -40°C; Contact Form: SPST; AEC Category: Q200

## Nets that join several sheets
AVDD: HMU (J21.1), UIR_Board_BQ79731 (6 pins), ISO_SPI (R402.1), ISOMonitor (J11.2)
GND: HMU (R405.2), UIR_Board_BQ79731 (27 pins), DaisyChain_2CH (12 pins), CurrentSense_2CH (16 pins), HV1 (5 pins), HV3 (5 pins), HV4 (5 pins), ISO_SPI (9 pins), Power (7 pins), ISOMonitor (12 pins)
GND_LV: HMU (J25.1), ISO_SPI (R31.1), Power (28 pins), ISOMonitor (J10.1)
HV12: UIR_Board_BQ79731 (R41.2 R42.2 R220.1 R310.2), Power (R14.2 R400.1)
TSREF: UIR_Board_BQ79731 (C95.1 R311.2 TP7.1 U16.43), CurrentSense_2CH (R212.2 R216.2)
VIO: HMU (J21.2), UIR_Board_BQ79731 (8 pins)
5V_HV: ISO_SPI (R404.1), Power (R401.2)
5V_LV: ISO_SPI (R26.1), Power (R1.2)
BATP: HMU (J24.2 R300.2 R406.2), HV1 (C500_HV1.1 R265_HV1.2)
BATP_L: HMU (R406.1), ISOMonitor (R5.2)
COMHN: UIR_Board_BQ79731 (U16.33), DaisyChain_2CH (5 pins)
COMHP: UIR_Board_BQ79731 (U16.34), DaisyChain_2CH (5 pins)
COMLN: UIR_Board_BQ79731 (U16.32), DaisyChain_2CH (5 pins)
COMLP: UIR_Board_BQ79731 (U16.31), DaisyChain_2CH (5 pins)
DIV_OUT: HV1 (C111_HV1.1 R268_HV1.1), GPIO_Matrix (R108.2)
DIV_OUT: HV3 (C111_HV3.1 R268_HV3.1), GPIO_Matrix (R114.2)
DIV_OUT: GPIO_Matrix (R125.2), HV4 (C111_HV4.1 R268_HV4.1)
GPIO1: UIR_Board_BQ79731 (J31.1 U16.21), GPIO_Matrix (R122.1)
GPIO2: UIR_Board_BQ79731 (J31.2 U16.20), GPIO_Matrix (R117.1)
GPIO5: UIR_Board_BQ79731 (J31.5 U16.17), GPIO_Matrix (R114.1)
GPIO6: UIR_Board_BQ79731 (J31.6 U16.16), GPIO_Matrix (R125.1)
GPIO11: UIR_Board_BQ79731 (J31.11 U16.11), GPIO_Matrix (R107.1)
GPIO12: UIR_Board_BQ79731 (J31.12 U16.10), GPIO_Matrix (R113.1)
HS_SW_DRV: GPIO_Matrix (R107.2), ISOMonitor (Q3.1 R67.2 U11.3)
ISO_VN: GPIO_Matrix (R100.2), ISOMonitor (C130.1 R66.1)
LS_SW_DRV: GPIO_Matrix (R113.2), ISOMonitor (Q2.1 R34.2 U2.3)
MISO_TX: UIR_Board_BQ79731 (J33.9 R500.1 U16.29), ISO_SPI (U4.11)
MOSI_RX: UIR_Board_BQ79731 (J33.10 R501.1 U16.28), ISO_SPI (U4.14)
nCS: UIR_Board_BQ79731 (J33.6 R502.1 U16.26), ISO_SPI (U4.12)
nFAULT: UIR_Board_BQ79731 (J33.7 R40.2 R503.1 U16.25), ISO_SPI (U5.3)
NTC1: CurrentSense_2CH (C82.1 R213.1), GPIO_Matrix (R117.2)
NTC2: CurrentSense_2CH (C84.1 R218.1), GPIO_Matrix (R122.2)
nUART/SPI: UIR_Board_BQ79731 (J30.1), ISO_SPI (U5.6)
OC1: UIR_Board_BQ79731 (J33.5 Q1.2 U16.24), ISO_SPI (R3.2 U5.4)
OC2: UIR_Board_BQ79731 (J33.3 Q1.5 U16.22), ISO_SPI (R4.2 U5.5)
RACKN: HMU (J22.1 R303.1), HV4 (C500_HV4.1 R265_HV4.2)
RACKP: HMU (J24.3), HV3 (C500_HV3.1 R265_HV3.2)
SCLK: UIR_Board_BQ79731 (J33.8 R504.1 U16.27), ISO_SPI (U4.13)
SRN1: UIR_Board_BQ79731 (U16.41), CurrentSense_2CH (C73.2 R199.2)
SRN2: UIR_Board_BQ79731 (U16.39), CurrentSense_2CH (C79.2 R209.2)
SRP1: UIR_Board_BQ79731 (U16.42), CurrentSense_2CH (C73.1 R196.2)
SRP2: UIR_Board_BQ79731 (U16.38), CurrentSense_2CH (C79.1 R206.2)
VF1: UIR_Board_BQ79731 (J32.8 U16.5), GPIO_Matrix (R108.1)
VF2: UIR_Board_BQ79731 (J32.7 U16.6), GPIO_Matrix (R100.1)

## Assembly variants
001: not fitted FID1 FID2 FID3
